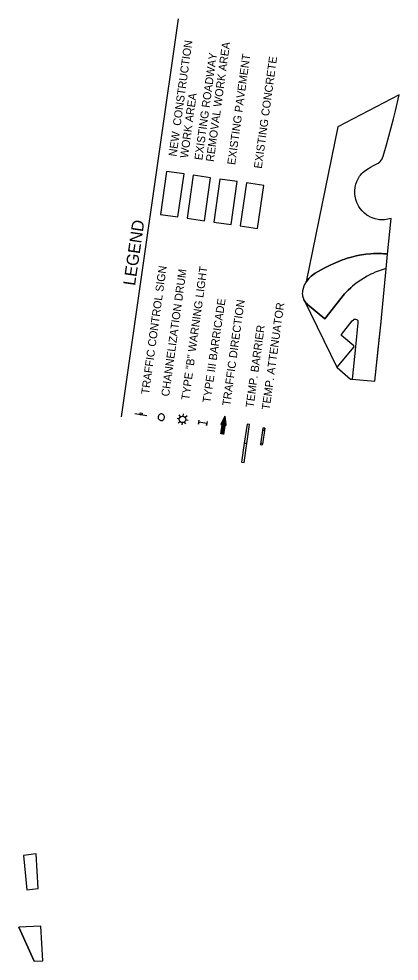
# Model space of a CAD drawing. Extents: x 1795987 to 1799689, y 243690 to 251545.
# Drawn here: x 1797401 to 1797771, y 248927 to 249845 of the extents above; entities that cross this region are included whole.
import ezdxf

# ---------------------------------------------------------------- set-up
doc = ezdxf.new("R2010")
doc.units = 0
for name, color, linetype in [('EP', 7, 'Continuous'), ('LEGEND', 7, 'Continuous'), ('Level 23', 7, 'Continuous'), ('Level 62', 7, 'Continuous')]:
    doc.layers.add(name, color=color, linetype=linetype)

# ---------------------------------------------------------------- blocks, each defined once
blk = doc.blocks.new('T21LR')
at = {"layer": 'Level 23'}
for p, q in [((0, 2), (31.5, 2)), ((0, -2), (31.5, -2))]:
    blk.add_line(p, q, dxfattribs=at)
blk.add_lwpolyline([(0, -2), (4, -2), (4, 2), (0, 2)], close=True, dxfattribs=at)
blk.add_circle((31.5, 0), 2, dxfattribs=at)

msp = doc.modelspace()

# ---------------------------------------------------------------- linework, layer by layer
at = {"layer": 'EP'}
for points in [[(1797729.6, 249614.5), (1797725.06, 249613.43), (1797720.59, 249612.17), (1797718.38, 249611.46), (1797716.07, 249610.65), (1797711.53, 249608.88), (1797707.05, 249606.92), (1797704.09, 249605.52), (1797698.21, 249602.54), (1797692.46, 249599.33), (1797689.69, 249597.57), (1797687.07, 249595.64), (1797685.82, 249594.61), (1797683.49, 249592.39), (1797682.41, 249591.18), (1797680.92, 249589.25), (1797679.27, 249586.52), (1797678.58, 249585.08), (1797677.76, 249582.84), (1797677.23, 249580.56), (1797677.08, 249579.4), (1797677.03, 249577.7), (1797677.08, 249576.85), (1797677.24, 249575.59), (1797677.73, 249573.72), (1797678.5, 249571.91), (1797679, 249571.02), (1797680.23, 249569.31), (1797680.97, 249568.49), (1797682.23, 249567.3), (1797698.94, 249553.14), (1797718.23, 249577.4), (1797719.34, 249578.73), (1797721.7, 249581.22), (1797724.22, 249583.54)], [(1797727.35, 249526.78), (1797715.33, 249536.89), (1797715.13, 249537.81), (1797725.68, 249551.14), (1797726.77, 249552.38), (1797727.3, 249552.78), (1797727.88, 249553), (1797728.19, 249553.03), (1797728.91, 249552.95), (1797729.88, 249552.56), (1797730.32, 249552.27), (1797730.86, 249551.75), (1797731.04, 249551.46), (1797731.22, 249550.83), (1797731.14, 249549.3), (1797728.72, 249526.01), (1797725.49, 249494.54), (1797724.72, 249494.11), (1797723.88, 249494.06), (1797711.05, 249505.41), (1797710.99, 249506.18), (1797727.39, 249525.78), (1797727.35, 249526.78)]]:
    msp.add_lwpolyline(points, dxfattribs=at)
at = {"layer": 'LEGEND'}
for p, q in [((1797501.08, 249457.88), (1797556.62, 249845.43)), ((1797525.67, 249458.85), (1797514.09, 249460.51)), ((1797558.59, 249457.81), (1797557.21, 249459.66)), ((1797560.96, 249458.42), (1797561.29, 249460.71)), ((1797564.91, 249458.56), (1797563.07, 249457.17)), ((1797601.64, 249458.41), (1797597.82, 249450.25)), ((1797602.77, 249449.47), (1797601.64, 249458.41)), ((1797557.35, 249455.71), (1797555.06, 249456.04)), ((1797556.1, 249451.96), (1797557.95, 249453.34)), ((1797560.06, 249452.09), (1797559.73, 249449.81)), ((1797563.81, 249450.85), (1797562.42, 249452.7)), ((1797563.67, 249454.8), (1797565.96, 249454.48)), ((1797598.75, 249450.1), (1797597.35, 249441.13)), ((1797597.82, 249450.25), (1797598.75, 249450.1)), ((1797600.43, 249440.65), (1797601.84, 249449.62)), ((1797601.84, 249449.62), (1797602.77, 249449.47))]:
    msp.add_line(p, q, dxfattribs=at)
for points in [[(1797555.87, 249652.47), (1797561.87, 249694.32), (1797544.97, 249696.74), (1797538.97, 249654.89)], [(1797581.77, 249648.76), (1797587.77, 249690.61), (1797570.87, 249693.03), (1797564.87, 249651.18)], [(1797607.67, 249645.05), (1797613.66, 249686.89), (1797596.77, 249689.32), (1797590.77, 249647.47)], [(1797633.57, 249641.34), (1797639.56, 249683.18), (1797622.67, 249685.6), (1797616.67, 249643.76)], [(1797518.91, 249459.82), (1797519.19, 249461.75), (1797521.12, 249461.47), (1797520.84, 249459.54)], [(1797625.73, 249450.35), (1797623.26, 249450.71), (1797620.6, 249432.15), (1797623.07, 249431.79)], [(1797623.07, 249431.79), (1797620.6, 249432.15), (1797617.94, 249413.59), (1797620.42, 249413.23)]]:
    msp.add_lwpolyline(points, close=True, dxfattribs=at)
for points in [[(1797584.46, 249453.09), (1797583.84, 249449.24), (1797584.15, 249451.17), (1797576.45, 249452.4), (1797576.14, 249450.48), (1797576.75, 249454.33)], [(1797599.51, 249453.85), (1797597.51, 249441.1)], [(1797599.9, 249454.7), (1797597.77, 249441.06)], [(1797597.92, 249450.46), (1797597.89, 249450.24)], [(1797600.3, 249455.55), (1797598.02, 249441.02)], [(1797598.32, 249451.31), (1797598.15, 249450.2)], [(1797600.7, 249456.4), (1797598.28, 249440.98)], [(1797598.72, 249452.16), (1797598.4, 249450.16)], [(1797601.09, 249457.24), (1797598.54, 249440.94)], [(1797599.11, 249453), (1797598.66, 249450.12)], [(1797601.49, 249458.09), (1797598.79, 249440.9)], [(1797601.71, 249457.83), (1797599.05, 249440.86)], [(1797601.83, 249456.9), (1797599.31, 249440.82)], [(1797601.95, 249455.97), (1797599.56, 249440.78)], [(1797602.06, 249455.04), (1797599.82, 249440.74)], [(1797602.18, 249454.11), (1797600.08, 249440.7)], [(1797602.3, 249453.19), (1797600.33, 249440.66)], [(1797602.42, 249452.26), (1797602, 249449.59)], [(1797602.53, 249451.33), (1797602.25, 249449.55)], [(1797602.65, 249450.4), (1797602.51, 249449.51)]]:
    msp.add_lwpolyline(points, dxfattribs=at)
msp.add_circle((1797560.51, 249455.26), 3.19, dxfattribs=at)
for start, end in [(81.84392, 261.84392), (261.84392, 81.84392)]:
    msp.add_arc((1797539.82, 249457.4), 3.18, start, end, dxfattribs=at)
at = {"layer": 'Level 62'}
for p, q in [((1797771.32, 249771.31), (1797711.7, 249740.2)), ((1797711.7, 249740.2), (1797680.92, 249589.25)), ((1797760.13, 249616.35), (1797763.47, 249651.01)), ((1797758.75, 249602.03), (1797760.13, 249616.35)), ((1797754.12, 249554.04), (1797758.75, 249602.03)), ((1797678.5, 249571.91), (1797711.05, 249505.41)), ((1797747.61, 249492.58), (1797754.06, 249553.61)), ((1797754.06, 249553.61), (1797754.12, 249554.04)), ((1797725.49, 249494.54), (1797747.61, 249492.58)), ((1797405.52, 249030.46), (1797408.82, 248997.09)), ((1797416.12, 248927.5), (1797401.09, 248960.67))]:
    msp.add_line(p, q, dxfattribs=at)
for points in [[(1797711.7, 249740.2), (1797680.92, 249589.25), (1797682.41, 249591.18), (1797683.49, 249592.39), (1797685.82, 249594.61), (1797687.07, 249595.64), (1797689.69, 249597.57), (1797692.46, 249599.33), (1797698.21, 249602.54), (1797704.09, 249605.52), (1797707.05, 249606.92), (1797711.53, 249608.88), (1797716.07, 249610.65), (1797718.38, 249611.46), (1797720.59, 249612.17), (1797725.06, 249613.43), (1797729.6, 249614.5), (1797732.65, 249615.1), (1797738.79, 249616.05), (1797743.87, 249616.57), (1797746.41, 249616.73), (1797750.24, 249616.83), (1797754.08, 249616.74), (1797756.01, 249616.62), (1797758.67, 249616.42), (1797760.12, 249616.35), (1797763.47, 249651.01), (1797761.9, 249650.54), (1797758.61, 249649.86), (1797756.96, 249649.67), (1797754.46, 249649.59), (1797752.26, 249649.73), (1797750.8, 249649.93), (1797747.93, 249650.57), (1797745.15, 249651.54), (1797743.36, 249652.35), (1797741.07, 249653.62), (1797739.98, 249654.34), (1797737.65, 249656.15), (1797736.56, 249657.14), (1797735.43, 249658.3), (1797733.39, 249660.81), (1797732.2, 249662.61), (1797731.49, 249663.86), (1797730.26, 249666.47), (1797729.19, 249669.53), (1797728.5, 249672.69), (1797728.29, 249674.3), (1797728.17, 249676.73), (1797728.2, 249678.21), (1797728.52, 249681.16), (1797728.91, 249683.1), (1797729.25, 249684.37), (1797730.11, 249686.86), (1797731.34, 249689.53), (1797732.86, 249692.03), (1797733.72, 249693.2), (1797735.13, 249694.84), (1797736.27, 249695.97), (1797738.75, 249698.01), (1797741.44, 249699.8), (1797743.31, 249700.88), (1797747.15, 249702.86), (1797749.73, 249704.17), (1797750.96, 249704.93), (1797752.4, 249706.07), (1797753.05, 249706.71), (1797753.91, 249707.77), (1797754.37, 249708.48), (1797755.14, 249709.99), (1797755.73, 249711.59), (1797756.67, 249714.92), (1797758.86, 249722.64), (1797763.53, 249739.46), (1797765.74, 249747.92), (1797767.68, 249755.71), (1797771.32, 249771.31), (1797711.7, 249740.2)], [(1797763.47, 249651.01), (1797761.9, 249650.54), (1797758.61, 249649.86), (1797756.96, 249649.67), (1797754.46, 249649.59), (1797752.26, 249649.73), (1797750.8, 249649.93), (1797747.93, 249650.57), (1797745.15, 249651.54), (1797743.36, 249652.35), (1797741.07, 249653.62), (1797739.98, 249654.34), (1797737.65, 249656.15), (1797736.56, 249657.14), (1797735.43, 249658.3), (1797733.39, 249660.81), (1797732.2, 249662.61), (1797731.49, 249663.86), (1797730.26, 249666.47), (1797729.19, 249669.53), (1797728.5, 249672.69), (1797728.29, 249674.3), (1797728.17, 249676.73), (1797728.2, 249678.21), (1797728.52, 249681.16), (1797728.91, 249683.1), (1797729.25, 249684.37), (1797730.11, 249686.86), (1797731.34, 249689.53), (1797732.86, 249692.03), (1797733.72, 249693.2), (1797735.13, 249694.84), (1797736.27, 249695.97), (1797738.75, 249698.01), (1797741.44, 249699.8), (1797743.31, 249700.88), (1797747.15, 249702.86), (1797749.73, 249704.17), (1797750.96, 249704.93), (1797752.4, 249706.07), (1797753.05, 249706.71), (1797753.91, 249707.77), (1797754.37, 249708.48), (1797755.14, 249709.99), (1797755.73, 249711.59), (1797756.67, 249714.92), (1797758.86, 249722.64), (1797763.53, 249739.46), (1797765.74, 249747.92), (1797767.68, 249755.71), (1797771.32, 249771.31)], [(1797590.77, 249647.47), (1797607.67, 249645.05), (1797613.66, 249686.89), (1797596.77, 249689.32), (1797590.77, 249647.47)], [(1797760.12, 249616.35), (1797758.67, 249616.42), (1797756.01, 249616.62), (1797754.08, 249616.74), (1797750.24, 249616.83), (1797746.41, 249616.73), (1797743.87, 249616.57), (1797738.79, 249616.05), (1797732.65, 249615.1), (1797729.6, 249614.5), (1797725.06, 249613.43), (1797720.59, 249612.17), (1797718.38, 249611.46), (1797716.07, 249610.65), (1797711.53, 249608.88), (1797707.05, 249606.92), (1797704.09, 249605.52), (1797698.21, 249602.54), (1797692.46, 249599.33), (1797689.69, 249597.57), (1797687.07, 249595.64), (1797685.82, 249594.61), (1797683.49, 249592.39), (1797682.41, 249591.18), (1797680.92, 249589.25)], [(1797758.75, 249602.03), (1797757.66, 249601.76), (1797752.72, 249600.3), (1797747.91, 249598.51), (1797745.56, 249597.49), (1797743.7, 249596.6), (1797740.05, 249594.65), (1797736.49, 249592.52), (1797734.17, 249591), (1797729.62, 249587.8), (1797725.98, 249585.01), (1797724.22, 249583.54), (1797721.7, 249581.22), (1797719.34, 249578.73), (1797718.23, 249577.4), (1797698.94, 249553.14), (1797682.23, 249567.3), (1797680.97, 249568.49), (1797680.23, 249569.31), (1797679, 249571.02), (1797678.5, 249571.91)], [(1797727.35, 249526.78), (1797715.33, 249536.89), (1797715.13, 249537.81), (1797725.68, 249551.14), (1797726.77, 249552.38), (1797727.3, 249552.78), (1797727.88, 249553), (1797728.19, 249553.03), (1797728.91, 249552.95), (1797729.88, 249552.56), (1797730.32, 249552.27), (1797730.86, 249551.75), (1797731.04, 249551.46), (1797731.22, 249550.83), (1797731.14, 249549.3), (1797728.72, 249526.01), (1797725.49, 249494.54)], [(1797747.61, 249492.58), (1797750.77, 249523.67), (1797754.06, 249553.61)], [(1797711.05, 249505.41), (1797710.99, 249506.18), (1797727.39, 249525.78), (1797727.35, 249526.78)], [(1797417.9, 249032.03), (1797405.52, 249030.46), (1797408.82, 248997.09), (1797420.02, 248998.34), (1797417.9, 249032.03)], [(1797422.34, 248961.52), (1797401.09, 248960.67), (1797416.12, 248927.5), (1797424.47, 248927.78), (1797422.34, 248961.52)]]:
    msp.add_lwpolyline(points, dxfattribs=at)

# ---------------------------------------------------------------- block references
at = {"layer": 'LEGEND', "xscale": 0.5000000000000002, "yscale": 0.5000000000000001, "rotation": -98.00678026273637}
msp.add_blockref('T21LR', (1797639.57, 249446.69), dxfattribs=at)

# ---------------------------------------------------------------- texts
at = {"layer": 'LEGEND'}
for s, height, rotation, p in [('NEW  CONSTRUCTION', 7.7999, 82.15693, (1797554.51, 249710.98)), ('REMOVAL WORK AREA', 7.7999, 82.15693, (1797590.79, 249705.84)), ('EXISTING ROADWAY', 7.7999, 82.15693, (1797579.66, 249707.38)), ('EXISTING PAVEMENT', 7.7999, 82.15693, (1797611.62, 249702.81)), ('EXISTING CONCRETE', 7.7999, 82.15693, (1797637.53, 249699.18)), ('WORK AREA', 7.8, 82.15693, (1797565.64, 249709.45)), ('LEGEND', 11.7, 81.6779, (1797514.15, 249585.02)), ('TRAFFIC CONTROL SIGN', 7.7999, 82.15693, (1797527.81, 249479.22)), ('CHANNELIZATION DRUM', 7.7999, 82.15693, (1797547.3, 249477.17)), ('TYPE "B" WARNING LIGHT', 7.7999, 82.15693, (1797566.85, 249473.62)), ('TYPE III BARRICADE', 7.7999, 81.6779, (1797587.54, 249470.96)), ('TRAFFIC DIRECTION', 7.7999, 82.15693, (1797606.79, 249468.03)), ('TEMP. ATTENUATOR', 7.7999, 82.15693, (1797645.19, 249464.08)), ('TEMP. BARRIER', 7.7999, 82.15693, (1797629.51, 249466.28))]:
    msp.add_text(s, height=height, rotation=rotation, dxfattribs=at).set_placement(p)

doc.saveas('drawing.dxf')
